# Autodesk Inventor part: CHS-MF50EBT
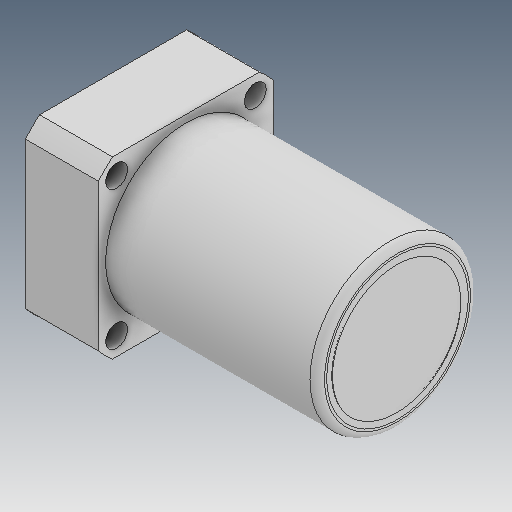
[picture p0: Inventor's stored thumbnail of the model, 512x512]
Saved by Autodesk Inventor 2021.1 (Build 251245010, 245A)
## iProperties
Created: 2019-04
Part Number: CHS-MF50EBT
Material: Ogólny
Document SubType Name: Modeling
Designer: user
Density: 1 g/cm^3
Appearance: Domyślna
Author: user
Revision Number: ÈÎºÎ
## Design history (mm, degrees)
feature "ÊäÈë1"
feature "ÊäÈë2"
node "Bryła1"
node "Bryła2"
